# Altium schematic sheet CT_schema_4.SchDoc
size 283 x 147 mm
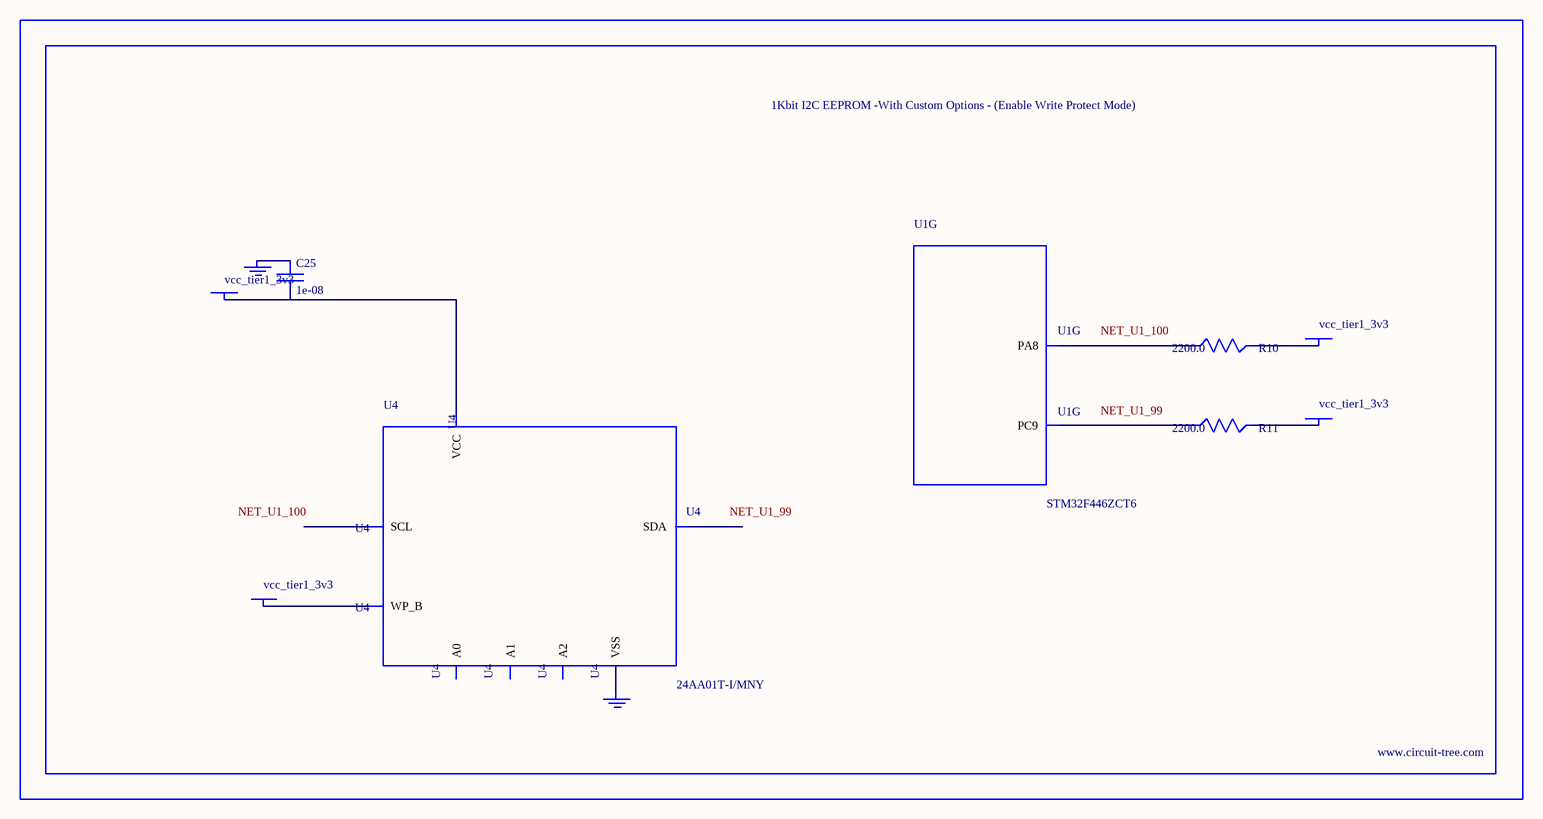
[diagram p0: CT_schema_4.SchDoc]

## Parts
BORDER3  (no value)
C25  1e-08  [C0402]
GND_INSTANCE_3_0  (no value)
GND_INSTANCE_3_1  (no value)
POWER_INSTANCE_3_0  vcc_tier1_3v3
POWER_INSTANCE_3_1  vcc_tier1_3v3
POWER_INSTANCE_3_2  vcc_tier1_3v3
POWER_INSTANCE_3_3  vcc_tier1_3v3
R10  2200.0  [R0603]
R11  2200.0  [R0603]
U1  STM32F446ZCT6  [LQFP144]  (part G of 12)
U4  24AA01T-I/MNY  [TDFN-8/6MM]

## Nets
NetC25_1: C25.1 GND_INSTANCE_3_0.0(GND)
NetC25_2: C25.2 POWER_INSTANCE_3_1.0(PWR) U4.8(VCC)
NetGND_INSTANCE_3_1_0: GND_INSTANCE_3_1.0(GND) U4.4(VSS)
NetPOWER_INSTANCE_3_0_0: POWER_INSTANCE_3_0.0(PWR) U4.7(WP_B)
NetPOWER_INSTANCE_3_2_0: POWER_INSTANCE_3_2.0(PWR) R11.2
NetPOWER_INSTANCE_3_3_0: POWER_INSTANCE_3_3.0(PWR) R10.2
NetR10_1: R10.1 U1.100(PA8)
NetR11_1: R11.1 U1.99(PC9)

Not connected (* = marked no-connect by the designer): U4 1(A0) 2(A1) 3(A2) 5(SDA) 6(SCL)

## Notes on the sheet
- Labels drawn without touching a wire or pin: NET_U1_99, NET_U1_100

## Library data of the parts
BORDER3 = BORDER_PAGE3
C25 = C0402C103K3RAC
GND_INSTANCE_3_0 GND_INSTANCE_3_1 = GND
POWER_INSTANCE_3_0-POWER_INSTANCE_3_3 = PWR
R10 R11 = RC0603JR-072K2L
